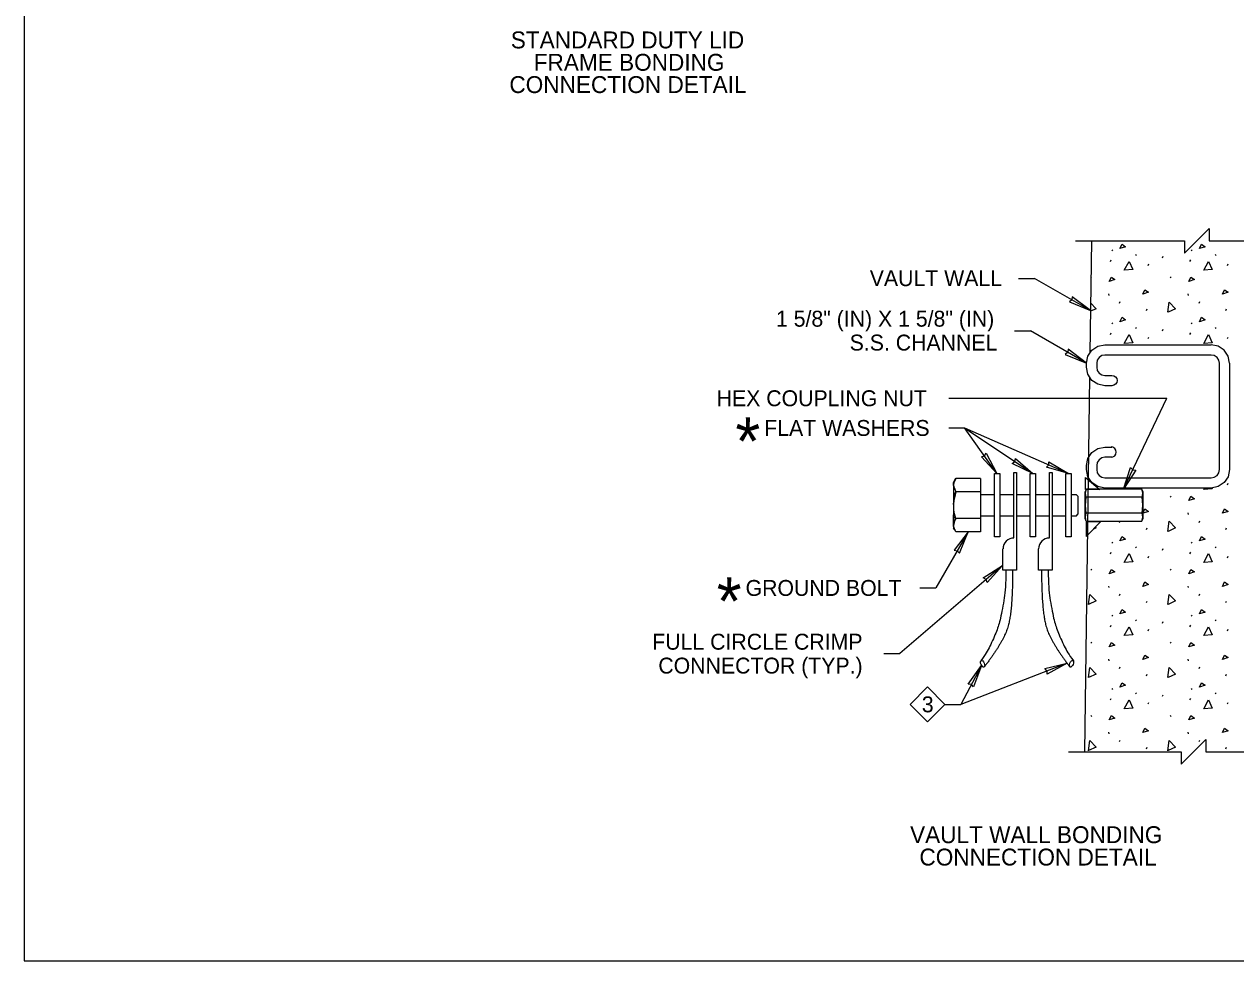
# Model space of a CAD drawing. Extents: x 99862 to 103151, y 100000 to 105076.
# Drawn here: x 99862 to 101081, y 103000 to 103941 of the extents above; entities that cross this region are included whole.
import ezdxf

# ---------------------------------------------------------------- set-up
doc = ezdxf.new("R2010")
doc.units = 0
for name, color, linetype in [('Level 1', 7, 'Continuous'), ('Level 10', 7, 'Continuous'), ('Level 13', 7, 'Continuous'), ('Level 15', 7, 'Continuous'), ('Level 20', 7, 'Continuous'), ('Level 3', 7, 'Continuous'), ('Level 30', 7, 'Continuous'), ('Level 5', 7, 'Continuous'), ('Level 60', 7, 'Continuous'), ('Level 8', 7, 'Continuous'), ('Level 9', 7, 'Continuous')]:
    doc.layers.add(name, color=color, linetype=linetype)

msp = doc.modelspace()

# ---------------------------------------------------------------- linework, layer by layer
at = {"layer": 'Level 1'}
msp.add_line((100934.2, 103586.7), (100929.1, 103209.8), dxfattribs=at)
msp.add_lwpolyline([(99862, 102999.5), (103151, 102999.5), (103151, 105075.5), (99862, 105075.5)], close=True, dxfattribs=at)
msp.add_lwpolyline([(100936.1, 103723.6), (100934.6, 103610.8)], dxfattribs=at)
at = {"layer": 'Level 10'}
for p, q in [((100824.6, 103468.6), (100838.4, 103468.6)), ((100843.9, 103468.6), (100858.1, 103468.6)), ((100860.7, 103468.6), (100874.5, 103468.6)), ((100879.8, 103468.6), (100893.9, 103468.6)), ((100896.6, 103468.6), (100910.4, 103468.6)), ((100915.6, 103468.6), (100920.6, 103468.6)), ((100922.8, 103466.4), (100920.6, 103468.6)), ((100922.8, 103449), (100922.8, 103466.4)), ((100838.4, 103446.8), (100824.6, 103446.8)), ((100858.1, 103446.8), (100843.9, 103446.8)), ((100874.5, 103446.8), (100860.7, 103446.8)), ((100893.9, 103446.8), (100879.8, 103446.8)), ((100910.4, 103446.8), (100896.6, 103446.8)), ((100920.6, 103446.8), (100915.6, 103446.8)), ((100920.6, 103446.8), (100922.8, 103449))]:
    msp.add_line(p, q, dxfattribs=at)
at = {"layer": 'Level 13'}
for p, q in [((100858.1, 103481.2), (100858.1, 103490.6)), ((100858.1, 103490.6), (100860.7, 103490.6)), ((100860.7, 103490.6), (100860.7, 103481.2)), ((100893.9, 103481.2), (100893.9, 103490.6)), ((100893.9, 103490.6), (100896.6, 103490.6)), ((100896.6, 103490.6), (100896.6, 103481.2)), ((100858.1, 103444.5), (100858.1, 103481.2)), ((100860.7, 103481.2), (100860.7, 103444.5)), ((100893.9, 103444.5), (100893.9, 103481.2)), ((100896.6, 103481.2), (100896.6, 103444.5)), ((100858.1, 103438.5), (100858.1, 103444.5)), ((100860.7, 103444.5), (100860.7, 103438.5)), ((100893.9, 103438.5), (100893.9, 103444.5)), ((100896.6, 103444.5), (100896.6, 103438.5)), ((100858.1, 103424.8), (100858.1, 103438.5)), ((100860.7, 103438.5), (100860.7, 103426.7)), ((100893.9, 103424.8), (100893.9, 103438.5)), ((100896.6, 103438.5), (100896.6, 103426.7)), ((100860.7, 103426.7), (100860.7, 103392.3)), ((100896.6, 103426.7), (100896.6, 103392.3)), ((100847.1, 103392.3), (100847.1, 103413.8)), ((100883, 103392.3), (100883, 103413.8)), ((100860.7, 103392.3), (100847.1, 103392.3)), ((100896.6, 103392.3), (100883, 103392.3))]:
    msp.add_line(p, q, dxfattribs=at)
for points in [[(100843.9, 103425.8), (100838.7, 103425.8), (100838.7, 103489.6), (100843.9, 103489.6)], [(100879.8, 103425.8), (100874.5, 103425.8), (100874.5, 103489.6), (100879.8, 103489.6)], [(100915.6, 103425.8), (100910.4, 103425.8), (100910.4, 103489.6), (100915.6, 103489.6)]]:
    msp.add_lwpolyline(points, close=True, dxfattribs=at)
for centre in [(100858.1, 103413.8), (100893.9, 103413.8)]:
    msp.add_arc(centre, 10.9, 90, 180, dxfattribs=at)
at = {"layer": 'Level 15'}
for p, q in [((100862.8, 103685.9), (100878.8, 103685.9)), ((100935.1, 103653.4), (100878.8, 103685.9)), ((100858.8, 103633.1), (100874.8, 103633.1)), ((100931.1, 103600.6), (100874.8, 103633.1)), ((100792.5, 103565.3), (101012.1, 103565.3)), ((100968.4, 103473.7), (101012.1, 103565.3)), ((100792.5, 103535.4), (100808.5, 103535.4)), ((100808.5, 103535.4), (100913, 103489.6)), ((100808.5, 103535.4), (100877.2, 103489.6)), ((100841, 103489.6), (100808.5, 103535.4)), ((100812, 103430.8), (100779.5, 103374.5)), ((100846.6, 103397.2), (100743.3, 103308.4)), ((100763.5, 103374.5), (100779.5, 103374.5)), ((100727.3, 103308.4), (100743.3, 103308.4)), ((100911.7, 103298.8), (100804.7, 103257.4)), ((100825.6, 103296.5), (100804.7, 103257.4)), ((100788.7, 103257.4), (100804.7, 103257.4))]:
    msp.add_line(p, q, dxfattribs=at)
for points in [[(100920.1, 103723.6), (101029.9, 103723.6), (101029.9, 103711.2), (101054.6, 103735.9), (101054.6, 103723.6), (101164.4, 103723.6)], [(100913.1, 103209.8), (101026.4, 103209.8), (101026.4, 103197.4), (101051.2, 103222.2), (101051.2, 103209.8), (101164.4, 103209.8)]]:
    msp.add_lwpolyline(points, dxfattribs=at)
for points in [[(100935.1, 103653.4), (100916.8, 103667.4), (100916.3, 103664.3), (100913.9, 103662.2)], [(100931.1, 103600.6), (100912.8, 103614.6), (100912.2, 103611.5), (100909.8, 103609.4)], [(100841, 103489.6), (100825.4, 103506.4), (100828.4, 103507.3), (100830.3, 103509.9)], [(100877.2, 103489.6), (100856.5, 103499.8), (100859.1, 103501.6), (100859.8, 103504.7)], [(100913, 103489.6), (100890.9, 103496), (100893.1, 103498.3), (100893.3, 103501.5)], [(100968.4, 103473.7), (100975.5, 103495.6), (100977.8, 103493.4), (100980.9, 103493)], [(100812, 103430.8), (100798, 103412.5), (100801.1, 103411.9), (100803.2, 103409.5)], [(100846.6, 103397.2), (100831.2, 103380.1), (100830.1, 103383), (100827.3, 103384.6)], [(100825.6, 103296.5), (100817.5, 103275), (100815.3, 103277.3), (100812.2, 103277.8)], [(100911.7, 103298.8), (100891.5, 103287.8), (100891.4, 103290.9), (100889.3, 103293.3)]]:
    msp.add_lwpolyline(points, close=True, dxfattribs=at)
at = {"layer": 'Level 20'}
msp.add_lwpolyline([(100771.1, 103274.9), (100788.7, 103257.4), (100771.1, 103239.8), (100753.6, 103257.4)], close=True, dxfattribs=at)
at = {"layer": 'Level 3'}
for p, q in [((100949.6, 103619.1), (101056.7, 103619.1)), ((101075.2, 103600.6), (101075.2, 103493.5)), ((101056.7, 103475), (100949.6, 103475))]:
    msp.add_line(p, q, dxfattribs=at)
for points in [[(100956.8, 103505.9), (100949.6, 103505.9), (100946.5, 103505.2), (100943.8, 103503.4), (100942, 103500.8), (100941.4, 103497.6), (100941.4, 103493.5), (100942, 103490.3), (100943.8, 103487.7), (100946.5, 103485.9), (100949.6, 103485.3), (101056.7, 103485.3), (101059.8, 103485.9), (101062.5, 103487.7), (101064.3, 103490.3), (101064.9, 103493.5), (101064.9, 103600.6), (101064.3, 103603.7), (101062.5, 103606.4), (101059.8, 103608.2), (101056.7, 103608.8), (100949.6, 103608.8), (100946.5, 103608.2), (100943.8, 103606.4), (100942, 103603.7), (100941.4, 103600.6), (100941.4, 103596.5), (100942, 103593.3), (100943.8, 103590.6), (100946.5, 103588.8), (100949.6, 103588.2), (100956.8, 103588.2), (100958.8, 103587.8), (100960.5, 103586.7), (100961.6, 103585.1), (100962, 103583.1), (100962, 103583), (100961.6, 103581.1), (100960.5, 103579.4), (100958.8, 103578.3), (100956.8, 103577.9), (100949.6, 103577.9), (100942.5, 103579.3), (100936.5, 103583.3), (100932.5, 103589.4), (100931.1, 103596.5), (100931.1, 103600.6), (100932.5, 103607.7), (100936.5, 103613.7), (100942.5, 103617.7), (100949.6, 103619.1), (100949.6, 103619.1)], [(101075.2, 103600.6), (101075.2, 103600.6), (101073.8, 103607.7), (101069.8, 103613.7), (101063.8, 103617.7), (101056.7, 103619.1), (101056.7, 103619.1)], [(100949.6, 103475), (100949.6, 103475), (100942.5, 103476.4), (100936.5, 103480.4), (100932.5, 103486.4), (100931.1, 103493.5), (100931.1, 103497.6), (100932.5, 103504.7), (100936.5, 103510.7), (100942.5, 103514.7), (100949.6, 103516.2), (100956.8, 103516.2)], [(100955.9, 103506), (100957.8, 103506.4), (100959.5, 103507.5), (100960.6, 103509.2), (100961, 103511.2), (100961, 103511.2), (100960.6, 103513.2), (100959.5, 103514.8), (100957.8, 103516), (100955.9, 103516.3)], [(101075.2, 103493.5), (101075.2, 103493.5), (101073.8, 103486.4), (101069.8, 103480.4), (101063.8, 103476.4), (101056.7, 103475), (101056.7, 103475)]]:
    msp.add_lwpolyline(points, dxfattribs=at)
at = {"layer": 'Level 30'}
for centre, major_axis in [((100826.6, 103298.3), (1.43, -3.35)), ((100916.1, 103298.3), (-1.43, -3.35))]:
    msp.add_ellipse(centre, major_axis=major_axis, ratio=0.472935, dxfattribs=at)
for points, degree in [([(100850, 103392.3), (100850, 103377.9), (100848.8, 103365), (100844.4, 103342.1), (100841.2, 103332), (100833.7, 103314.9), (100829.5, 103307.8), (100824.7, 103301.3)], 3), ([(100856.8, 103392.3), (100856.8, 103347.8), (100845.5, 103317.3), (100828.4, 103295.3)], 2), ([(100885.9, 103392.3), (100885.9, 103347.8), (100897.2, 103317.3), (100914.3, 103295.3)], 2), ([(100892.7, 103392.3), (100892.7, 103377.9), (100893.9, 103365), (100898.3, 103342.1), (100901.5, 103332), (100909, 103314.9), (100913.2, 103307.8), (100918, 103301.3)], 3)]:
    msp.add_open_spline(points, degree=degree, dxfattribs=at)
at = {"layer": 'Level 5'}
for p, q in [((100929.8, 103471), (100931, 103473.9)), ((100929.8, 103444.2), (100929.8, 103471)), ((100987.1, 103465.7), (100930.9, 103465.7)), ((100986.9, 103473.9), (100931, 103473.9)), ((100986.9, 103473.9), (100931.1, 103473.9)), ((100988.1, 103471), (100986.9, 103473.9)), ((100988.1, 103444.2), (100988.1, 103471)), ((100930.9, 103441.6), (100929.8, 103444.2)), ((100987.1, 103449.7), (100930.8, 103449.7)), ((100930.9, 103441.6), (100987, 103441.6)), ((100930.9, 103441.5), (100987, 103441.5)), ((100987, 103441.6), (100988.1, 103444.2))]:
    msp.add_line(p, q, dxfattribs=at)
for points in [[(100930.8, 103449.7), (100930, 103457.7), (100930.9, 103465.6)], [(100930.9, 103465.6), (100930.1, 103469.8), (100931, 103473.9)], [(100987.1, 103465.7), (100987.8, 103469.8), (100986.9, 103473.9)], [(100987.1, 103449.8), (100987.9, 103457.8), (100987.1, 103465.7)], [(100930.9, 103441.6), (100930, 103445.7), (100930.9, 103449.8)], [(100987, 103441.6), (100987.9, 103445.7), (100987.1, 103449.8)]]:
    msp.add_lwpolyline(points, dxfattribs=at)
at = {"layer": 'Level 60'}
msp.add_line((99862, 102999.5), (99862, 102999.5), dxfattribs=at)
at = {"layer": 'Level 8'}
for p, q in [((100956.6, 103714.6), (100957.3, 103713.5)), ((100980.5, 103710.1), (100981.3, 103709)), ((101036.6, 103714.6), (101037.3, 103713.5)), ((101060.5, 103710.1), (101061.3, 103709)), ((100955.3, 103702.9), (100956, 103704.5)), ((100993.2, 103698.8), (100993.9, 103700.4)), ((101007.6, 103706.6), (101008.3, 103708.2)), ((101035.3, 103702.9), (101036, 103704.5)), ((101073.2, 103698.8), (101073.9, 103700.4)), ((100935.6, 103687.1), (100936.1, 103686.4)), ((101015.4, 103687.4), (101016.1, 103686.4)), ((100953.3, 103670.4), (100953.5, 103668.8)), ((100964.4, 103661), (100965.1, 103662.6)), ((101033.3, 103670.4), (101033.5, 103668.8)), ((101044.4, 103661), (101045.1, 103662.6)), ((100991.4, 103653.7), (100992.1, 103655.3)), ((101071.4, 103653.7), (101072.1, 103655.3)), ((100956.6, 103641.1), (100957.3, 103640)), ((100980.5, 103636.6), (100981.3, 103635.5)), ((101036.6, 103641.1), (101037.3, 103640)), ((101060.5, 103636.6), (101061.3, 103635.5)), ((100955.3, 103629.4), (100956, 103631)), ((100993.2, 103625.3), (100993.9, 103626.9)), ((101007.6, 103633.1), (101008.3, 103634.7)), ((101035.3, 103629.4), (101036, 103631)), ((101073.2, 103625.3), (101073.9, 103626.9)), ((100935.4, 103613.9), (100936, 103613)), ((101073.2, 103478.3), (101073.9, 103479.9)), ((100969.5, 103473.9), (100970, 103475)), ((101015.4, 103466.9), (101016.1, 103465.8)), ((101049.2, 103473.5), (101050, 103475)), ((100964.4, 103440.4), (100964.9, 103441.6)), ((101033.3, 103449.9), (101033.5, 103448.3)), ((101044.4, 103440.4), (101045.1, 103442)), ((100991.4, 103433.2), (100992.1, 103434.8)), ((101071.4, 103433.2), (101072.1, 103434.8)), ((100956.6, 103420.6), (100957.3, 103419.5)), ((101036.6, 103420.6), (101037.3, 103419.5)), ((100955.3, 103408.8), (100956, 103410.4)), ((100980.5, 103416), (100981.3, 103415)), ((100993.2, 103404.8), (100993.9, 103406.4)), ((101007.6, 103412.6), (101008.3, 103414.2)), ((101035.3, 103408.8), (101036, 103410.4)), ((101060.5, 103416), (101061.3, 103415)), ((101073.2, 103404.8), (101073.9, 103406.4)), ((100935.4, 103393.4), (100936.1, 103392.3)), ((101015.4, 103393.4), (101016.1, 103392.3)), ((100953.3, 103376.4), (100953.5, 103374.8)), ((100964.4, 103366.9), (100965.1, 103368.5)), ((101033.3, 103376.4), (101033.5, 103374.8)), ((101044.4, 103366.9), (101045.1, 103368.5)), ((100991.4, 103359.7), (100992.1, 103361.3)), ((101071.4, 103359.7), (101072.1, 103361.3)), ((100956.6, 103347), (100957.3, 103346)), ((101036.6, 103347), (101037.3, 103346)), ((100955.3, 103335.3), (100956, 103336.9)), ((100980.5, 103342.5), (100981.3, 103341.5)), ((100993.2, 103331.3), (100993.9, 103332.9)), ((101007.6, 103339.1), (101008.3, 103340.6)), ((101035.3, 103335.3), (101036, 103336.9)), ((101060.5, 103342.5), (101061.3, 103341.5)), ((101073.2, 103331.3), (101073.9, 103332.9)), ((100935.4, 103319.9), (100936.1, 103318.8)), ((101015.4, 103319.9), (101016.1, 103318.8)), ((100953.3, 103302.9), (100953.5, 103301.3)), ((100964.4, 103293.4), (100965.1, 103295)), ((101033.3, 103302.9), (101033.5, 103301.3)), ((101044.4, 103293.4), (101045.1, 103295)), ((100991.4, 103286.1), (100992.1, 103287.7)), ((101071.4, 103286.1), (101072.1, 103287.7)), ((100956.6, 103273.5), (100957.3, 103272.5)), ((101036.6, 103273.5), (101037.3, 103272.5)), ((100955.3, 103261.8), (100956, 103263.4)), ((100980.5, 103269), (100981.3, 103268)), ((100993.2, 103257.8), (100993.9, 103259.3)), ((101007.6, 103265.5), (101008.3, 103267.1)), ((101035.3, 103261.8), (101036, 103263.4)), ((101060.5, 103269), (101061.3, 103268)), ((101073.2, 103257.8), (101073.9, 103259.3)), ((100935.4, 103246.4), (100936.1, 103245.3)), ((101015.4, 103246.4), (101016.1, 103245.3)), ((100953.3, 103229.3), (100953.5, 103227.7)), ((100964.4, 103219.9), (100965.1, 103221.5)), ((101033.3, 103229.3), (101033.5, 103227.7)), ((101044.4, 103219.9), (101045.1, 103221.5)), ((100991.4, 103212.6), (100992.1, 103214.2)), ((101071.4, 103212.6), (101072.1, 103214.2))]:
    msp.add_line(p, q, dxfattribs=at)
for points in [[(100964.8, 103715.8), (100966.9, 103720.3), (100970.5, 103717.6), (100964.8, 103715.8)], [(101044.8, 103715.8), (101046.9, 103720.3), (101050.5, 103717.6), (101044.8, 103715.8)], [(100969.2, 103694), (100974, 103703), (100977.7, 103694.7), (100969.4, 103694)], [(101049.2, 103694), (101054, 103703), (101057.7, 103694.7), (101049.4, 103694)], [(100954, 103682.8), (100956.2, 103687.2), (100959.7, 103684.6), (100954, 103682.8)], [(101034, 103682.8), (101036.2, 103687.2), (101039.7, 103684.6), (101034, 103682.8)], [(100987.9, 103670.1), (100990, 103674.5), (100993.6, 103671.9), (100987.9, 103670.1)], [(101067.9, 103670.1), (101070, 103674.5), (101073.6, 103671.9), (101067.9, 103670.1)], [(100935.2, 103661.2), (100940.8, 103655.4), (100935.1, 103652.8)], [(101013, 103651.8), (101014.4, 103662), (101020.8, 103655.4), (101013.2, 103651.9)], [(100964.8, 103642.3), (100966.9, 103646.7), (100970.5, 103644.1), (100964.8, 103642.3)], [(101044.8, 103642.3), (101046.9, 103646.7), (101050.5, 103644.1), (101044.8, 103642.3)], [(100969.2, 103620.5), (100974, 103629.5), (100977.7, 103621.2), (100969.4, 103620.5)], [(101049.2, 103620.5), (101054, 103629.5), (101057.7, 103621.2), (101049.4, 103620.5)], [(100977.4, 103475), (100977.7, 103474.2), (100974.8, 103473.9)], [(101034, 103462.3), (101036.2, 103466.7), (101039.7, 103464.1), (101034, 103462.3)], [(101057.3, 103475.1), (101057.7, 103474.2), (101049.4, 103473.5)], [(100988.1, 103449.9), (100990, 103454), (100993.6, 103451.4), (100988.1, 103449.6)], [(101067.9, 103449.6), (101070, 103454), (101073.6, 103451.4), (101067.9, 103449.6)], [(100934.4, 103441), (100934.4, 103441.5), (100934.9, 103441)], [(101013, 103431.3), (101014.4, 103441.5), (101020.8, 103434.9), (101013.2, 103431.4)], [(100940.1, 103435.6), (100940.8, 103434.9), (100938.2, 103433.7)], [(100964.8, 103421.8), (100966.9, 103426.2), (100970.5, 103423.6), (100964.8, 103421.8)], [(101044.8, 103421.8), (101046.9, 103426.2), (101050.5, 103423.6), (101044.8, 103421.8)], [(100969.2, 103400), (100974, 103409), (100977.7, 103400.7), (100969.4, 103400)], [(101049.2, 103400), (101054, 103409), (101057.7, 103400.7), (101049.4, 103400)], [(100954, 103388.8), (100956.2, 103393.2), (100959.7, 103390.6), (100954, 103388.8)], [(101034, 103388.8), (101036.2, 103393.2), (101039.7, 103390.6), (101034, 103388.8)], [(100987.9, 103376.1), (100990, 103380.5), (100993.6, 103377.9), (100987.9, 103376.1)], [(101067.9, 103376.1), (101070, 103380.5), (101073.6, 103377.9), (101067.9, 103376.1)], [(100933, 103357.8), (100934.4, 103368), (100940.8, 103361.4), (100933.2, 103357.9)], [(101013, 103357.8), (101014.4, 103368), (101020.8, 103361.4), (101013.2, 103357.9)], [(100964.8, 103348.3), (100966.9, 103352.7), (100970.5, 103350.1), (100964.8, 103348.3)], [(101044.8, 103348.3), (101046.9, 103352.7), (101050.5, 103350.1), (101044.8, 103348.3)], [(100969.2, 103326.5), (100974, 103335.5), (100977.7, 103327.2), (100969.4, 103326.5)], [(101049.2, 103326.5), (101054, 103335.5), (101057.7, 103327.2), (101049.4, 103326.5)], [(100954, 103315.3), (100956.2, 103319.7), (100959.7, 103317), (100954, 103315.3)], [(101034, 103315.3), (101036.2, 103319.7), (101039.7, 103317), (101034, 103315.3)], [(100987.9, 103302.6), (100990, 103307), (100993.6, 103304.4), (100987.9, 103302.6)], [(101067.9, 103302.6), (101070, 103307), (101073.6, 103304.4), (101067.9, 103302.6)], [(100933, 103284.3), (100934.4, 103294.5), (100940.8, 103287.9), (100933.2, 103284.4)], [(101013, 103284.3), (101014.4, 103294.5), (101020.8, 103287.9), (101013.2, 103284.4)], [(100964.8, 103274.8), (100966.9, 103279.2), (100970.5, 103276.6), (100964.8, 103274.8)], [(101044.8, 103274.8), (101046.9, 103279.2), (101050.5, 103276.6), (101044.8, 103274.8)], [(100969.2, 103253), (100974, 103262), (100977.7, 103253.7), (100969.4, 103253)], [(101049.2, 103253), (101054, 103262), (101057.7, 103253.7), (101049.4, 103253)], [(100954, 103241.8), (100956.2, 103246.2), (100959.7, 103243.5), (100954, 103241.8)], [(101034, 103241.8), (101036.2, 103246.2), (101039.7, 103243.5), (101034, 103241.8)], [(100987.9, 103229.1), (100990, 103233.5), (100993.6, 103230.8), (100987.9, 103229.1)], [(101067.9, 103229.1), (101070, 103233.5), (101073.6, 103230.8), (101067.9, 103229.1)], [(100933, 103210.8), (100934.4, 103221), (100940.8, 103214.4), (100933.2, 103210.9)], [(101013, 103210.8), (101014.4, 103221), (101020.8, 103214.4), (101013.2, 103210.9)]]:
    msp.add_lwpolyline(points, dxfattribs=at)
for points in [[(100944.6, 103473.4), (100930, 103473.4), (100930, 103485.7)], [(100945.4, 103441), (100930.8, 103441), (100930.8, 103426.3)]]:
    msp.add_lwpolyline(points, close=True, dxfattribs=at)
at = {"layer": 'Level 9'}
for p, q in [((100824.6, 103484.6), (100799.5, 103484.6)), ((100797.4, 103469.9), (100799, 103469.9))]:
    msp.add_line(p, q, dxfattribs=at)
for points in [[(100797.4, 103477.6), (100797.4, 103478.1), (100797.4, 103480.7), (100798.7, 103483), (100799.5, 103484.6)], [(100799.5, 103484.6), (100798.5, 103482.3), (100797.7, 103480.3), (100797.4, 103478.1)], [(100797.4, 103480.7), (100797.4, 103480.6), (100797.4, 103480.6)], [(100797.4, 103477.9), (100797.4, 103477.9), (100797.6, 103476.1), (100798.5, 103473.7), (100799.5, 103471.1)], [(100797.4, 103477.6), (100797.4, 103472.6), (100797.4, 103465.9), (100797.4, 103458.3), (100797.4, 103457.1), (100797.4, 103449.5), (100797.4, 103442.8), (100797.4, 103437.8), (100797.4, 103437.2), (100797.4, 103434.7), (100798.6, 103433), (100797.4, 103434.7), (100798.5, 103433.2)], [(100824.6, 103484.6), (100824.6, 103471.1), (100824.6, 103444.2), (100824.6, 103430.8), (100799.5, 103430.8), (100798.5, 103433.2)], [(100799.5, 103444.2), (100799.5, 103444.2), (100798.4, 103449.2), (100797.7, 103452.7), (100797.5, 103457.8), (100797.4, 103458.6), (100798.4, 103466.5), (100798.5, 103467.4), (100799.5, 103471.1), (100799.5, 103471.1)], [(100824.6, 103471.1), (100799.5, 103471.1), (100798.5, 103466.6), (100797.7, 103462.5), (100797.4, 103458.3)], [(100797.4, 103437.4), (100797.4, 103437.7), (100797.4, 103447.9)], [(100797.4, 103445.4), (100799.5, 103445.4)], [(100799.5, 103444.2), (100798.5, 103442.4), (100798.4, 103441.8), (100797.4, 103438), (100797.4, 103437.7), (100797.4, 103442.8), (100797.4, 103442.8)], [(100824.6, 103444.2), (100799.5, 103444.2), (100798.7, 103442.7), (100798.4, 103441.9), (100797.5, 103438.6), (100797.4, 103437.8)], [(100798.5, 103433.2), (100797.7, 103435.1), (100797.4, 103437.4)], [(100799.5, 103430.8), (100798.6, 103433), (100797.5, 103435.8), (100797.4, 103437.2)]]:
    msp.add_lwpolyline(points, dxfattribs=at)

# ---------------------------------------------------------------- texts
at = {"layer": 'Level 20'}
for s, height, p in [('STANDARD DUTY LID', 17, (100351.7, 103917.2)), ('FRAME BONDING', 17, (100374.8, 103894.7)), ('CONNECTION DETAIL', 17, (100350.3, 103872.3)), ('VAULT WALL', 16, (100713, 103678.1)), ('1 5/8" (IN) X 1 5/8" (IN)', 16, (100618.6, 103637.3)), ('S.S. CHANNEL', 16, (100692.8, 103613.3)), ('HEX COUPLING NUT', 16, (100558.9, 103557.3)), ('*', 48, (100577.8, 103498.1)), ('FLAT WASHERS', 16, (100606.8, 103527.4)), ('*', 48, (100559, 103337.2)), ('GROUND BOLT', 16, (100588, 103366.5)), ('FULL CIRCLE CRIMP ', 16, (100494.1, 103312.4)), ('CONNECTOR (TYP.)', 16, (100500.2, 103288.4)), ('3', 16, (100765.4, 103249.4)), ('VAULT WALL BONDING', 17, (100753.6, 103117.8)), ('CONNECTION DETAIL', 17, (100763, 103095.3))]:
    msp.add_text(s, height=height, dxfattribs=at).set_placement(p)

doc.saveas('drawing.dxf')
